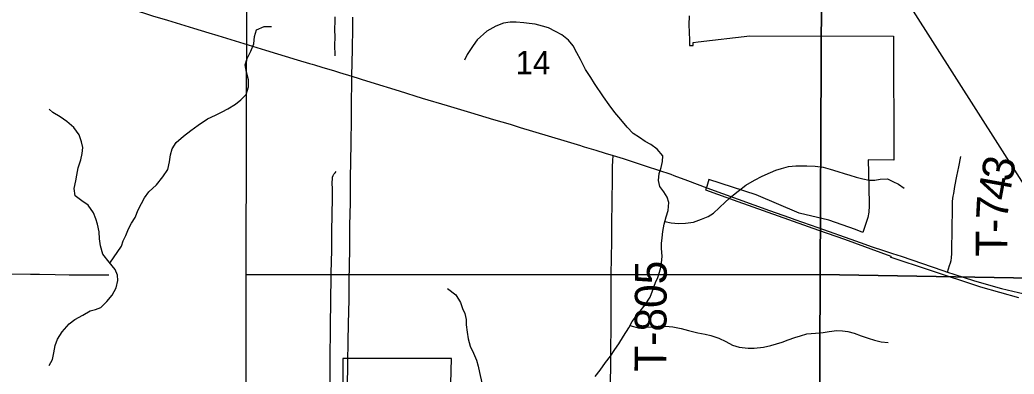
# Model space of a CAD drawing. Extents: x 0 to 34, y 0 to 22.
# Drawn here: x 9.229 to 11.007, y 16.918 to 17.551 of the extents above; entities that cross this region are included whole.
import ezdxf

# ---------------------------------------------------------------- set-up
doc = ezdxf.new("R2010")
doc.units = 0
for name, color, linetype in [('GM_X_Corporation', 7, 'Continuous'), ('GM_X_Minor_River', 7, 'Continuous'), ('GM_X_Rail_Line', 7, 'Continuous'), ('GM_X_Section', 7, 'Continuous'), ('GM_X_Section_Text', 7, 'Continuous'), ('GM_X_State_Route', 7, 'Continuous'), ('GM_X_Township_Road', 7, 'Continuous'), ('GM_X_Township_Road_Text', 7, 'Continuous'), ('GM_X_US_Route', 7, 'Continuous')]:
    doc.layers.add(name, color=color, linetype=linetype)

msp = doc.modelspace()

# ---------------------------------------------------------------- linework, layer by layer
at = {"layer": 'GM_X_Corporation'}
for points in [[(10.4255, 17.558), (10.4249, 17.5418), (10.4254, 17.5288), (10.4262, 17.5147), (10.4261, 17.5051), (10.4326, 17.5053), (10.4325, 17.5105), (10.4415, 17.5118), (10.5343, 17.5226), (10.7907, 17.5217), (10.7918, 17.3), (10.7455, 17.3007), (10.7467, 17.254), (10.7474, 17.2183), (10.7467, 17.2073), (10.7451, 17.1975), (10.736, 17.1709), (10.7232, 17.1763), (10.6756, 17.1932), (10.6221, 17.2057), (10.5452, 17.238), (10.4609, 17.2657), (10.4569, 17.2531), (10.4546, 17.2471), (10.5125, 17.2263), (10.6569, 17.1749), (10.7034, 17.1588), (10.7862, 17.1286), (10.7863, 17.1263), (10.7863, 17.127), (10.8546, 17.1042), (10.9467, 17.0739), (11.0144, 17.0549)], [(9.9927, 16.6526), (10.0005, 16.9455), (9.8063, 16.9455), (9.8063, 16.8935)]]:
    msp.add_lwpolyline(points, dxfattribs=at)
at = {"layer": 'GM_X_Minor_River'}
for points in [[(9.3898, 17.116), (9.4102, 17.1463), (9.4133, 17.1558), (9.418, 17.1658), (9.4231, 17.1773), (9.4281, 17.1877), (9.4351, 17.1977), (9.4405, 17.2115), (9.4463, 17.223), (9.4517, 17.2326), (9.4594, 17.2438), (9.4732, 17.2559), (9.4846, 17.2706), (9.493, 17.2837), (9.4961, 17.2971), (9.4981, 17.3096), (9.5012, 17.3203), (9.5082, 17.3315), (9.5215, 17.3428), (9.5342, 17.3534), (9.5476, 17.3628), (9.564, 17.3742), (9.5783, 17.3806), (9.5906, 17.3866), (9.6007, 17.3918), (9.6142, 17.4001), (9.6238, 17.4083), (9.6335, 17.4176), (9.6377, 17.431), (9.6374, 17.4439), (9.6337, 17.4574), (9.6315, 17.4707), (9.635, 17.4818), (9.6415, 17.4952), (9.6469, 17.5082), (9.6481, 17.5212), (9.652, 17.5334), (9.6655, 17.5394), (9.6784, 17.5389)], [(10.1298, 17.5459), (10.1162, 17.5471), (10.1052, 17.5468), (10.0938, 17.5449), (10.0797, 17.54), (10.0637, 17.531), (10.0466, 17.5155), (10.0393, 17.5049), (10.0287, 17.489), (10.0241, 17.4791)], [(10.2574, 16.9134), (10.2666, 16.9251), (10.2761, 16.9384), (10.2849, 16.9501), (10.2929, 16.9619), (10.2998, 16.9721), (10.3082, 16.9858), (10.3174, 17.0005), (10.3239, 17.0115), (10.3353, 17.0274), (10.3467, 17.0418), (10.3559, 17.0551), (10.3601, 17.0668), (10.3651, 17.0813), (10.3693, 17.0907), (10.3743, 17.1059), (10.3759, 17.1158), (10.377, 17.1287), (10.3763, 17.142), (10.3764, 17.1515), (10.3772, 17.1614), (10.3783, 17.1724), (10.3807, 17.1857), (10.3845, 17.199), (10.388, 17.2104), (10.3895, 17.2244), (10.3865, 17.2343), (10.3801, 17.2438), (10.3729, 17.2534), (10.3707, 17.264), (10.3722, 17.2765), (10.3757, 17.2868), (10.378, 17.2978), (10.3784, 17.3077), (10.3686, 17.3199), (10.3569, 17.3279), (10.3466, 17.3333), (10.3368, 17.3405), (10.3254, 17.3478), (10.3148, 17.3589), (10.3031, 17.373), (10.2929, 17.3852), (10.2827, 17.3989), (10.2721, 17.4134), (10.2563, 17.437), (10.2495, 17.4477), (10.24, 17.4622), (10.2314, 17.4801), (10.2246, 17.4923), (10.2182, 17.5045), (10.2095, 17.5144), (10.1977, 17.5243), (10.1867, 17.5301), (10.1742, 17.5366), (10.1632, 17.54), (10.1503, 17.5431), (10.1393, 17.5447), (10.1298, 17.5459)], [(9.2808, 16.9331), (9.2872, 16.9437), (9.2895, 16.9559), (9.2919, 16.9689), (9.2962, 16.98), (9.3046, 16.9935), (9.3167, 17.0078), (9.3272, 17.0153), (9.3414, 17.0232), (9.3541, 17.0311), (9.3639, 17.0332), (9.3737, 17.0369), (9.3844, 17.0474), (9.3936, 17.059), (9.4009, 17.0717), (9.4036, 17.085), (9.403, 17.0949), (9.399, 17.1046), (9.3881, 17.118), (9.3771, 17.1322), (9.3726, 17.1469), (9.3708, 17.1598), (9.3702, 17.1719), (9.3672, 17.1858), (9.3643, 17.1956), (9.3606, 17.2058), (9.3509, 17.2196), (9.3397, 17.2277), (9.3277, 17.2365), (9.3255, 17.2494), (9.3286, 17.2631), (9.3307, 17.2734), (9.333, 17.2864), (9.3376, 17.3005), (9.34, 17.3123), (9.3413, 17.3226), (9.3387, 17.3332), (9.3347, 17.3452), (9.3253, 17.3587), (9.3125, 17.3694), (9.3006, 17.3774), (9.2879, 17.3855), (9.2808, 17.3916)], [(10.382, 17.1903), (10.3932, 17.1883), (10.4065, 17.1871), (10.419, 17.1874), (10.4334, 17.1896), (10.4475, 17.1945), (10.4593, 17.1994), (10.4692, 17.2054), (10.4795, 17.2149), (10.4905, 17.2259), (10.5019, 17.2357), (10.513, 17.2448), (10.5271, 17.2553), (10.5427, 17.2644), (10.5564, 17.2716), (10.5708, 17.2783), (10.5803, 17.2821), (10.5906, 17.2855), (10.6035, 17.2888), (10.6164, 17.2899), (10.6358, 17.2898), (10.651, 17.2894), (10.6654, 17.2878), (10.6779, 17.2839), (10.6916, 17.2797), (10.7026, 17.2762), (10.7132, 17.2735), (10.7245, 17.27), (10.7359, 17.267), (10.7473, 17.2646), (10.7576, 17.2646), (10.7671, 17.2661), (10.7803, 17.2668), (10.7898, 17.2622), (10.8001, 17.2572), (10.8103, 17.2503)], [(9.9934, 17.0708), (10.0081, 17.0593), (10.0168, 17.0456), (10.0202, 17.0353), (10.0244, 17.0258), (10.0266, 17.0155), (10.0269, 17.006), (10.0288, 16.9927), (10.0303, 16.9809), (10.034, 16.9676), (10.04, 16.955), (10.0453, 16.9425), (10.0483, 16.9322), (10.0506, 16.9208), (10.0547, 16.9021)], [(10.3197, 17.0044), (10.3367, 17.0001), (10.3481, 17.0015), (10.3614, 17.0022), (10.3728, 17.003), (10.3831, 17.0033), (10.3963, 17.0025), (10.4115, 16.9994), (10.4244, 16.9955), (10.4411, 16.9916), (10.4544, 16.9889), (10.4646, 16.987), (10.4787, 16.9823), (10.4912, 16.9758), (10.5033, 16.9693), (10.515, 16.9658), (10.531, 16.9643), (10.5416, 16.9642), (10.5587, 16.966), (10.5716, 16.969), (10.5815, 16.972), (10.5921, 16.975), (10.6024, 16.9791), (10.6146, 16.9833), (10.6248, 16.9863), (10.6359, 16.9896), (10.6514, 16.9907), (10.6651, 16.9922), (10.6757, 16.994), (10.6898, 16.9958), (10.6997, 16.9954), (10.7095, 16.9942), (10.7205, 16.9908), (10.733, 16.9862), (10.7455, 16.9819), (10.7569, 16.9785), (10.7687, 16.9757), (10.7816, 16.9742)]]:
    msp.add_lwpolyline(points, dxfattribs=at)
at = {"layer": 'GM_X_Rail_Line'}
msp.add_lwpolyline([(11.5404, 16.5859), (11.5289, 16.5995), (11.4762, 16.6651), (11.2305, 16.9587), (11.1455, 17.0668), (11.0594, 17.202), (10.8227, 17.5728), (10.5824, 17.9507), (10.5577, 17.9852), (10.5319, 18.0169), (10.4959, 18.0492), (10.4634, 18.0702), (10.4059, 18.1032), (10.3351, 18.1361), (9.8403, 18.3254), (9.7839, 18.3345), (9.7112, 18.3327), (9.6038, 18.3127), (9.5474, 18.32), (9.5165, 18.3345), (9.4983, 18.3528), (9.4692, 18.3928), (9.2764, 18.7478), (9.2289, 18.8396)], dxfattribs=at)
at = {"layer": 'GM_X_Section'}
for points in [[(9.6357, 18.1129), (10.6649, 18.109), (10.6598, 17.0956), (9.6334, 17.0953)], [(11.6666, 18.0929), (11.6623, 17.0784), (10.6598, 17.0956), (10.6649, 18.109)], [(9.6334, 17.0953), (10.6598, 17.0956), (10.6556, 16.0807), (9.6337, 16.083)], [(10.6598, 17.0956), (11.6623, 17.0784), (11.6595, 16.0824), (11.4045, 16.0641), (11.2434, 16.0596), (11.1308, 16.065), (10.9857, 16.0787), (10.6556, 16.0807)]]:
    msp.add_lwpolyline(points, close=True, dxfattribs=at)
at = {"layer": 'GM_X_State_Route'}
for points in [[(9.3944, 17.5801), (9.4496, 17.5633), (9.4536, 17.5621), (9.4658, 17.5584), (9.4925, 17.5503), (9.5391, 17.5361), (9.5668, 17.5276), (9.5824, 17.5229), (9.6678, 17.4969), (9.7243, 17.4798), (9.7469, 17.473), (9.7514, 17.4717)], [(9.7514, 17.4717), (9.7554, 17.4705), (9.7688, 17.4664), (9.7914, 17.4597), (9.8003, 17.4571), (9.8226, 17.4503)]]:
    msp.add_lwpolyline(points, dxfattribs=at)
at = {"layer": 'GM_X_Township_Road'}
for points in [[(9.7926, 17.4867), (9.7922, 17.5069), (9.7923, 17.519), (9.7922, 17.5348), (9.7924, 17.548), (9.7924, 17.5561)], [(10.2862, 17.095), (10.2869, 17.1264), (10.2871, 17.1545), (10.2875, 17.1857), (10.2886, 17.267), (10.2886, 17.2888), (10.2888, 17.2991), (10.2897, 17.3084)], [(10.8876, 17.1001), (10.8914, 17.1116), (10.893, 17.1166), (10.8939, 17.1209), (10.8946, 17.1257), (10.8953, 17.1333), (10.8954, 17.1396), (10.8955, 17.1461), (10.896, 17.1694), (10.8962, 17.1873), (10.8964, 17.2032), (10.8967, 17.2211), (10.8968, 17.2263), (10.8973, 17.2318), (10.8978, 17.2359), (10.8986, 17.2407), (10.9009, 17.253), (10.9044, 17.2715), (10.9077, 17.2884), (10.9112, 17.3067)], [(9.7849, 17.0509), (9.785, 17.0642), (9.7852, 17.0767), (9.7855, 17.0885), (9.7856, 17.0985), (9.7863, 17.139), (9.7865, 17.1514), (9.7865, 17.1577), (9.7868, 17.1732), (9.7875, 17.2324), (9.7875, 17.248), (9.7873, 17.2602), (9.7876, 17.2667), (9.788, 17.2697), (9.7889, 17.2727), (9.7904, 17.2754), (9.7924, 17.2778), (9.7944, 17.2801)], [(9.104, 17.0981), (9.1059, 17.0982), (9.1214, 17.0986), (9.1461, 17.0984), (9.1864, 17.0974), (9.2082, 17.0972), (9.2474, 17.0967)], [(9.2474, 17.0967), (9.264, 17.0965), (9.2919, 17.0959), (9.3168, 17.0954)], [(9.3168, 17.0954), (9.3198, 17.0954), (9.3508, 17.0951), (9.3725, 17.0951), (9.3876, 17.0952)], [(10.2842, 16.8064), (10.2843, 16.8384), (10.2846, 16.8663), (10.2854, 16.9348), (10.2862, 17.0277), (10.2862, 17.095)], [(9.7843, 17.0013), (9.7843, 17.0141), (9.7847, 17.0389), (9.7849, 17.0509)], [(9.7833, 16.8521), (9.7834, 16.8593), (9.7836, 16.8686), (9.7837, 16.884), (9.7836, 16.8871), (9.7836, 16.9026), (9.7836, 16.9151), (9.7834, 16.9305), (9.7837, 16.9399), (9.7838, 16.9523), (9.7837, 16.9647), (9.784, 16.9801), (9.784, 16.9863), (9.7843, 16.9955), (9.7843, 17.0013)]]:
    msp.add_lwpolyline(points, dxfattribs=at)
at = {"layer": 'GM_X_US_Route'}
for p, q in [((9.8211, 17.3306), (9.8216, 17.3737)), ((10.234, 17.3254), (10.2379, 17.3243))]:
    msp.add_line(p, q, dxfattribs=at)
for points in [[(9.8226, 17.4503), (9.8233, 17.4985), (9.8239, 17.5367), (9.8243, 17.5559)], [(9.8216, 17.3737), (9.8219, 17.3978), (9.8225, 17.4441), (9.8226, 17.4503)], [(9.8226, 17.4503), (9.8505, 17.4416), (9.8525, 17.441), (9.8563, 17.4398), (9.907, 17.4243), (9.9484, 17.4113), (9.9929, 17.3979), (10.0344, 17.3855), (10.0759, 17.3729), (10.1052, 17.3644), (10.1129, 17.362)], [(10.1129, 17.362), (10.1233, 17.3586), (10.2012, 17.3351), (10.2311, 17.3262), (10.234, 17.3254)], [(9.8185, 17.1434), (9.819, 17.1838), (9.8197, 17.2242), (9.8201, 17.2646), (9.8206, 17.3019), (9.821, 17.3266), (9.8211, 17.3306)], [(10.2379, 17.3243), (10.2584, 17.318), (10.2753, 17.3128), (10.2897, 17.3084)], [(10.2897, 17.3084), (10.3075, 17.3029), (10.3487, 17.2897), (10.3927, 17.2749), (10.3982, 17.2729), (10.4226, 17.2638), (10.4571, 17.2509)], [(10.4571, 17.2509), (10.5694, 17.2104), (10.6051, 17.1974), (10.6145, 17.1941), (10.6554, 17.1797), (10.7229, 17.156), (10.7396, 17.1502), (10.7513, 17.146), (10.7751, 17.1382), (10.7895, 17.1334), (10.8046, 17.1284), (10.8794, 17.1029), (10.8876, 17.1001), (10.8986, 17.0963), (10.9009, 17.0956), (10.934, 17.0852), (10.9606, 17.0773), (10.9844, 17.0709), (11.0144, 17.0636), (11.0386, 17.0584), (11.0658, 17.0532), (11.0902, 17.0491), (11.106, 17.047), (11.1166, 17.0457)], [(9.8173, 17.0509), (9.8176, 17.0845), (9.8185, 17.1404), (9.8185, 17.1434)], [(9.7773, 16.6512), (9.7806, 16.6587), (9.7843, 16.6683), (9.7893, 16.6821), (9.7936, 16.6946), (9.7965, 16.7037), (9.8014, 16.7218), (9.8049, 16.737), (9.8079, 16.7523), (9.8098, 16.7646), (9.8116, 16.7801), (9.8128, 16.7988), (9.8137, 16.8206), (9.8147, 16.8922), (9.8153, 16.9389), (9.8158, 16.9762), (9.8163, 17.0074), (9.8173, 17.0509)]]:
    msp.add_lwpolyline(points, dxfattribs=at)

# ---------------------------------------------------------------- texts
at = {"layer": 'GM_X_Section_Text'}
msp.add_text('14', height=0.04186, rotation=0, dxfattribs=at).set_placement((10.1151, 17.4537))
at = {"layer": 'GM_X_Township_Road_Text'}
for s, height, rotation, p in [('3', 0.0568, 79.5657, (11.003, 17.2601)), ('4', 0.0568, 79.6342, (10.9967, 17.2257)), ('7', 0.0568, 87.0742, (10.9952, 17.1926)), ('-', 0.0568, 89.477, (10.995, 17.1699)), ('T', 0.0568, 89.4857, (10.9946, 17.1274)), ('T-805', 0.05682, 89.7179, (10.3846, 16.9219))]:
    msp.add_text(s, height=height, rotation=rotation, dxfattribs=at).set_placement(p)

doc.saveas('drawing.dxf')
